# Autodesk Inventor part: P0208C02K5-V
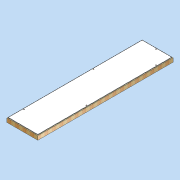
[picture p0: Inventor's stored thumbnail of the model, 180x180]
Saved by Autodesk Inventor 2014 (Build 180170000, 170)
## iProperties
Created: 2011-04
Part Number: P0208C02K5-V
Document SubType Name: Modeling
Designer: david.appleford
Density: 0.22684 g/cm^3
Description: 0.5w x 2w 02 Ceiling Panel - Locks 5
Mass: 24000 g
Surface Area: 30461.3 cm^2
Volume: 105802 cm^3
Cost Center: £92.00
Material: Generic
Appearance: Wood (Pine)
Justset: False
Author: david.appleford
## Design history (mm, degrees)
sketch "Sketch1"
  geometry: L1 (0, 0)-(610, 0); L2 (610, 0)-(610, 2440); L3 (610, 2440)-(0, 2440); L4 (0, 2440)-(0, 0); L5 (34, 2406)-(576, 2406); L6 (576, 2406)-(576, 34); L7 (576, 34)-(34, 34); L8 (34, 34)-(34, 2406)
  constraints: 16 end point, 4 parallel, 2 perpendicular, 1 horizontal, 3 other
  dimensions: "d0" = 610 distance between parallel lines of L2 L4 (= 0.5 x w); "d1" = 2440 distance between parallel lines of L1 L3 (= 2 x w); "d2" = 34 distance between parallel lines of L5 L3 (= 0.5 x t)
extrude "Extrusion1" new body sketch "Sketch1" distance "d3" = 68 (= t); taper "d4" = 0 deg
sketch "Sketch2"
  geometry: L1 (576, 2406)-(576, 34) reference; L2 (34, 2406)-(576, 2406) reference; L3 (34, 34)-(34, 2406) reference; L4 (576, 34)-(34, 34) reference; L5 (566, 2396)-(566, 44); L6 (566, 44)-(44, 44); L7 (44, 44)-(44, 2396); L8 (44, 2396)-(566, 2396); 1 further point
  constraints: 8 end point, 3 other
  dimensions: "d5" = 10 distance between parallel lines of L8 L2
extrude "Extrusion2" join sketch "Sketch2" distance "d6" = 9; taper "d7" = 0 deg
sketch "Sketch3"
  geometry: L1 (-44, 2396)-(-566, 2396) reference; L2 (-566, 2396)-(-566, 44) reference; L3 (-44, 44)-(-44, 2396) reference; L4 (-566, 44)-(-44, 44) reference; 1 further point
extrude "Extrusion3" join sketch "Sketch3" distance "d8" = 6 (= sw); taper "d9" = 0 deg
sketch "Sketch4"
  geometry: L1 (34, 2406)-(576, 2406) reference; L2 (576, 2406)-(576, 34) reference; L3 (576, 34)-(34, 34) reference; L4 (34, 34)-(34, 2406) reference; 6 further points
  constraints: 2 vertical alignment
  dimensions: "d10" = 28 distance from line of point (305, 2378) L1 (= k); "d13" = 28 distance from line of point (62, 305) L4 (= k); "d14" = 305 horizontal distance of point (305, 2378) point (0, 0) (= 0.25 x w); "d16" = 305 vertical distance of point (62, 305) point (0, 0) (= 0.25 x w); "d17" = 1220 distance of point (62, 305) point (62, 1525) (= w); "d19" = 610 vertical distance of point (548, 915) point (62, 305) (= 0.5 x w); "d20" = 1220 distance of point (548, 915) point (548, 2135) (= w)
hole "Hole1" sketch "Sketch4" at (305, 2378), (62, 1525), (62, 305), (548, 2135), (548, 915) diameter "d22" = 16.3; stored, may be unused: countersink angle "d26" = 90 deg, drill point angle "d28" = 118 deg; dims "d23" = 6, "d24" = 4, "d25" = 2, "d27" = 9
chamfer "Chamfer1" distance "d29" = 3; stored, may be unused: second distance "d30" = 2, angle "d31" = 45 deg
body "Solid1"
node "Projected Loop1"
other parameters: "w" = 1220 [user parameter; used in 7 equation terms], "t" = 68 [user parameter; used in 2 equation terms], "e" = 16 [user parameter], "sw" = 6 [user parameter; used in 1 equation term], "sc" = 9 [user parameter], "sf" = 12 [user parameter], "k" = 28 [user parameter; used in 2 equation terms], "hd" = 12 [user parameter]
